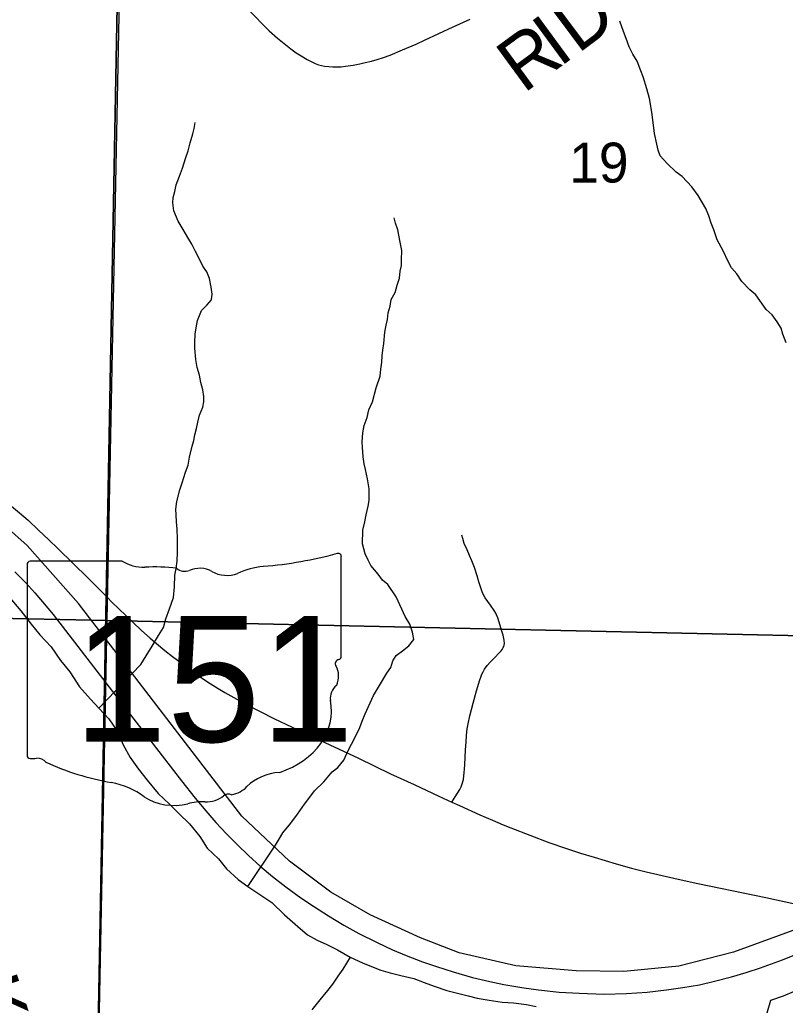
# Model space of a CAD drawing. Extents: x 0 to 34, y 0 to 22.
# Drawn here: x 11.383 to 12.186, y 18.575 to 19.609 of the extents above; entities that cross this region are included whole.
import ezdxf

# ---------------------------------------------------------------- set-up
doc = ezdxf.new("R2010")
doc.units = 0
for name, color, linetype in [('GM_X_Corporation', 7, 'Continuous'), ('GM_X_Major_River', 7, 'Continuous'), ('GM_X_Minor_River', 7, 'Continuous'), ('GM_X_Rail_Line', 7, 'Continuous'), ('GM_X_Section_Text', 7, 'Continuous'), ('GM_X_State_Location', 7, 'Continuous'), ('GM_X_State_Route', 7, 'Continuous'), ('GM_X_State_Shield', 7, 'Continuous'), ('GM_X_Township_Road', 7, 'Continuous'), ('GM_X_Township_Road_Text', 7, 'Continuous')]:
    doc.layers.add(name, color=color, linetype=linetype)

msp = doc.modelspace()

# ---------------------------------------------------------------- linework, layer by layer
at = {"layer": 'GM_X_Corporation'}
for points in [[(11.5001, 20.4), (10.6, 20.4), (10.6, 17.5523), (10.9447, 17.5459), (11.0329, 17.5442), (11.4477, 17.5329), (11.4514, 17.7789), (11.4741, 19.003), (11.486, 19.6423), (11.498, 20.2911)], [(10.6, 20.0026), (10.6, 18.9967), (11.4752, 18.9783), (11.4952, 19.9838)], [(12.5051, 19.9749), (12.4906, 18.9558), (11.4752, 18.9783), (11.4952, 19.9838)], [(10.6, 18.9967), (10.6, 18.0532), (11.4565, 18.0343), (11.4752, 18.9783)], [(11.4752, 18.9783), (12.4906, 18.9558), (12.4638, 18.0185), (11.4565, 18.0343)]]:
    msp.add_lwpolyline(points, close=True, dxfattribs=at)
msp.add_lwpolyline([(16.7661, 20.4), (11.5001, 20.4), (11.498, 20.2911), (11.486, 19.6423), (11.4741, 19.003), (11.4514, 17.7789), (11.4477, 17.5329), (11.8073, 17.526), (12.504, 17.5091), (12.7693, 17.5027), (12.7967, 17.502), (13.2742, 17.4966), (14.0954, 17.4811)], dxfattribs=at)
at = {"layer": 'GM_X_Major_River'}
for points in [[(11.373, 19.0022), (11.3846, 18.9884), (11.3954, 18.9745), (11.4047, 18.9633), (11.4163, 18.9506), (11.4263, 18.9363), (11.436, 18.9244), (11.4461, 18.9086), (11.4577, 18.8959), (11.4665, 18.8862), (11.4769, 18.875), (11.4859, 18.8618), (11.4918, 18.8479), (11.4992, 18.8347), (11.5081, 18.8224), (11.517, 18.8108), (11.5286, 18.7969), (11.5405, 18.7857), (11.5505, 18.7757), (11.5616, 18.7648), (11.5725, 18.7517), (11.5802, 18.7394), (11.5921, 18.7282), (11.6003, 18.7177), (11.6126, 18.7065), (11.6229, 18.6991), (11.6352, 18.6909), (11.6478, 18.6824), (11.6612, 18.6694), (11.6751, 18.6571), (11.6854, 18.6485), (11.6954, 18.643), (11.7057, 18.6382), (11.7167, 18.6327), (11.7301, 18.6249), (11.7431, 18.6191), (11.7526, 18.6151), (11.7621, 18.6114), (11.772, 18.6085), (11.7834, 18.6057), (11.7967, 18.6025), (11.8078, 18.5985), (11.8181, 18.5945), (11.8314, 18.5902), (11.8413, 18.5877), (11.8538, 18.5844)], [(12.1676, 18.5667), (12.1712, 18.58), (12.1847, 18.5844), (12.196, 18.5895)], [(11.8538, 18.5844), (11.8633, 18.5819), (11.8759, 18.5799), (11.8895, 18.5778), (11.9013, 18.5772), (11.9149, 18.5752), (11.9252, 18.5731)]]:
    msp.add_lwpolyline(points, dxfattribs=at)
at = {"layer": 'GM_X_Minor_River'}
for points in [[(12.1873, 19.2697), (12.184, 19.2789), (12.1821, 19.2849), (12.1779, 19.2918), (12.1727, 19.299), (12.1666, 19.3048), (12.1557, 19.32), (12.1493, 19.3254), (12.1409, 19.3341), (12.1357, 19.3421), (12.13, 19.3482), (12.1266, 19.3551), (12.1214, 19.3661), (12.115, 19.3779), (12.1116, 19.3882), (12.1086, 19.3951), (12.1063, 19.4031), (12.1033, 19.4107), (12.095, 19.4244), (12.0883, 19.4335), (12.0784, 19.4442), (12.072, 19.4488), (12.0626, 19.458), (12.0554, 19.466), (12.0531, 19.4717), (12.0516, 19.4781), (12.0494, 19.4892), (12.048, 19.501), (12.0465, 19.5116), (12.0439, 19.5261), (12.0413, 19.5363), (12.0375, 19.5489), (12.0349, 19.555), (12.0312, 19.5653), (12.0266, 19.5725), (12.0229, 19.5801), (12.0195, 19.5889), (12.0169, 19.5965), (12.0131, 19.6071)], [(11.4665, 18.8862), (11.5105, 18.9321), (11.5162, 18.9412), (11.5224, 18.9514), (11.5292, 18.9624), (11.5342, 18.9708), (11.5369, 18.9799), (11.5407, 18.9905), (11.5446, 19.0023), (11.5458, 19.0137), (11.5462, 19.0258), (11.5474, 19.033), (11.5485, 19.0406), (11.549, 19.0501), (11.549, 19.0566), (11.549, 19.0642), (11.5487, 19.0741), (11.548, 19.0817), (11.5476, 19.0893), (11.5473, 19.095), (11.5481, 19.1033), (11.5515, 19.1155), (11.5538, 19.1227), (11.5573, 19.1341), (11.56, 19.1413), (11.5615, 19.1496), (11.5642, 19.1614), (11.5662, 19.1671), (11.5673, 19.1732), (11.5689, 19.1796), (11.5704, 19.1865), (11.572, 19.1937), (11.5754, 19.202), (11.5766, 19.2077), (11.5766, 19.2134), (11.5755, 19.2203), (11.5733, 19.2282), (11.5722, 19.2358), (11.5695, 19.2438), (11.5681, 19.2522), (11.567, 19.264), (11.567, 19.2701), (11.5674, 19.2788), (11.5686, 19.2853), (11.5701, 19.2932), (11.5743, 19.3035), (11.5797, 19.3092), (11.5846, 19.3148), (11.5854, 19.3209), (11.5843, 19.3281), (11.5825, 19.3373), (11.5798, 19.3441), (11.5757, 19.3502), (11.5719, 19.3574), (11.5674, 19.3662), (11.564, 19.3731), (11.5599, 19.3803), (11.555, 19.3887), (11.5497, 19.3974), (11.5452, 19.4081), (11.5441, 19.4165), (11.5445, 19.4222), (11.546, 19.4286), (11.5476, 19.4355), (11.551, 19.4446), (11.5541, 19.4529), (11.5572, 19.4632), (11.5603, 19.4711), (11.5622, 19.4795), (11.5649, 19.489), (11.5664, 19.4947), (11.5676, 19.5007)], [(11.6229, 18.6991), (11.6516, 18.7426), (11.6558, 18.7495), (11.6596, 18.7555), (11.668, 18.7657), (11.6749, 18.7752), (11.6821, 18.7854), (11.6879, 18.793), (11.6928, 18.7995), (11.7023, 18.8089), (11.7111, 18.8195), (11.7172, 18.824), (11.7233, 18.8316), (11.7279, 18.8419), (11.7348, 18.8551), (11.7402, 18.8661), (11.7428, 18.8726), (11.7459, 18.8805), (11.7494, 18.8881), (11.7547, 18.8995), (11.7608, 18.9101), (11.7685, 18.923), (11.7727, 18.9291), (11.775, 18.9359), (11.7784, 18.9416), (11.7849, 18.9465), (11.7917, 18.9518), (11.7967, 18.9582), (11.7956, 18.9662), (11.7926, 18.9746), (11.7877, 18.9826), (11.7843, 18.9902), (11.7783, 19.0031), (11.7696, 19.0161), (11.764, 19.0207), (11.7594, 19.0268), (11.7519, 19.0359), (11.7489, 19.0416), (11.7459, 19.0481), (11.7429, 19.0588), (11.7433, 19.0732), (11.7456, 19.0819), (11.7468, 19.0892), (11.7491, 19.0983), (11.7499, 19.1043), (11.75, 19.1165), (11.7481, 19.1268), (11.7463, 19.1367), (11.7448, 19.1427), (11.7437, 19.15), (11.7429, 19.1602), (11.7426, 19.1659), (11.7434, 19.1751), (11.7449, 19.183), (11.748, 19.1914), (11.7496, 19.1993), (11.7534, 19.2077), (11.7573, 19.2225), (11.7615, 19.2346), (11.7623, 19.2419), (11.7634, 19.2494), (11.7638, 19.2559), (11.7643, 19.262), (11.7654, 19.2688), (11.7666, 19.281), (11.7678, 19.2882), (11.7693, 19.2943), (11.7701, 19.3011), (11.772, 19.3083), (11.7732, 19.3151), (11.7774, 19.3224), (11.7793, 19.3303), (11.7817, 19.3375), (11.7824, 19.3447), (11.784, 19.3508), (11.784, 19.3569), (11.7841, 19.3664), (11.7826, 19.3752), (11.78, 19.3881), (11.7777, 19.3953), (11.7762, 19.401)], [(11.7301, 18.6249), (11.7224, 18.6124), (11.717, 18.6052), (11.7117, 18.5968), (11.7063, 18.59), (11.6983, 18.5802), (11.6899, 18.5699)]]:
    msp.add_lwpolyline(points, dxfattribs=at)
at = {"layer": 'GM_X_Rail_Line'}
for points in [[(12.2022, 18.6557), (12.1321, 18.6303), (12.0749, 18.6156), (12.0173, 18.61), (11.9673, 18.6107), (11.9039, 18.6159), (11.8444, 18.6294), (11.8039, 18.6454), (11.7512, 18.6696), (11.7099, 18.6932), (11.6663, 18.7259), (11.6166, 18.7731), (11.445, 18.9962), (11.3914, 19.0571), (11.3294, 19.1119)], [(11.3785, 19.0292), (11.3898, 19.0178), (11.3993, 19.0073), (11.4075, 18.9978), (11.4185, 18.9845), (11.5032, 18.8747), (11.553, 18.81), (11.5675, 18.792), (11.5786, 18.7785), (11.5892, 18.7663), (11.6005, 18.7544), (11.6116, 18.7431), (11.6235, 18.7316), (11.6358, 18.7204), (11.6487, 18.7098), (11.6626, 18.6988), (11.6784, 18.6873), (11.6926, 18.6778), (11.7073, 18.6683), (11.7233, 18.6587), (11.7393, 18.6499), (11.7584, 18.6404), (11.7745, 18.6327), (11.7889, 18.6267), (11.806, 18.6202), (11.8207, 18.6151), (11.8382, 18.6095), (11.8585, 18.6037), (11.8766, 18.5996), (11.8911, 18.5964), (11.9121, 18.5927), (11.9278, 18.5906), (11.9492, 18.5883), (11.9702, 18.5871), (11.9966, 18.5863), (12.0199, 18.5869), (12.0415, 18.5883), (12.0619, 18.5908), (12.079, 18.5931), (12.0965, 18.5961), (12.1124, 18.5997), (12.13, 18.6043), (12.1456, 18.609), (12.1606, 18.6139), (12.1837, 18.6221), (12.2276, 18.6399)]]:
    msp.add_lwpolyline(points, dxfattribs=at)
at = {"layer": 'GM_X_State_Route'}
for points in [[(11.2749, 19.171), (11.2808, 19.1672), (11.3014, 19.1533), (11.3151, 19.1438), (11.3325, 19.1312), (11.3484, 19.1196), (11.3612, 19.1096), (11.3708, 19.1019), (11.3832, 19.0913), (11.3922, 19.0834), (11.4032, 19.0731), (11.414, 19.0628), (11.4236, 19.0537), (11.4552, 19.0226), (11.4647, 19.0133), (11.4755, 19.0023), (11.4801, 18.9977)], [(11.4801, 18.9977), (11.502, 18.9765), (11.5112, 18.9678), (11.5203, 18.9597), (11.5358, 18.9468), (11.5437, 18.9406), (11.5555, 18.9316), (11.5694, 18.9215), (11.5751, 18.9175), (11.5832, 18.9122), (11.5916, 18.9069), (11.5987, 18.9027), (11.6111, 18.8957), (11.6212, 18.8903), (11.6358, 18.8827), (11.6501, 18.8756), (11.6883, 18.8574), (11.7388, 18.8337), (11.7725, 18.8175), (11.7973, 18.8062), (11.8232, 18.7938), (11.8367, 18.7876), (11.8448, 18.784), (11.8662, 18.7743), (11.8794, 18.7686), (11.8905, 18.7639), (11.8987, 18.7606), (11.9385, 18.7454), (11.957, 18.7391), (11.9717, 18.7343), (11.9861, 18.7298), (12.0091, 18.723), (12.0253, 18.7185), (12.0407, 18.7145), (12.0575, 18.7107), (12.0742, 18.7068), (12.0949, 18.7023), (12.166, 18.6876), (12.1964, 18.6811)]]:
    msp.add_lwpolyline(points, dxfattribs=at)
at = {"layer": 'GM_X_State_Shield'}
for p, q in [((11.491, 19.0404), (11.3945, 19.0404)), ((11.7208, 18.9407), (11.7208, 19.0454)), ((11.3913, 19.037), (11.3913, 18.8369)), ((11.7208, 18.9407), (11.7208, 18.9407))]:
    msp.add_line(p, q, dxfattribs=at)
for centre, major_axis, start_param, end_param in [((11.395, 19.0374), (0.00382, 0), 1.712693, 3.28349), ((11.514, 19.0637), (0.037, 0), 4.042523, 4.731795), ((11.6034, 19.3133), (0.3495, 0), 4.814394, 5.042369), ((11.7172, 19.0458), (0.00367, 0), 6.141152, 7.989035), ((11.5263, 18.9281), (0.133, 0), 1.404758, 1.657858), ((11.5565, 19.0385), (0.0107, 0), 3.836095, 5.185415), ((11.5722, 19.0153), (0.0222, 0), 0.950623, 2.079405), ((11.6008, 19.047), (0.0267, 0), 4.081561, 5.145723), ((11.648, 18.9793), (0.0703, 0), 1.699011, 2.107814), ((11.72, 18.933), (0.00568, 0), 1.883978, 3.671073), ((11.7169, 18.9403), (0.00393, 0), 5.05454, 6.418171), ((11.6839, 18.9198), (0.0341, 0), 5.934695, 6.695948), ((11.734, 18.8969), (0.0248, 0), 2.387724, 3.262537), ((11.623, 18.8836), (0.0874, 0), 5.101752, 6.440018), ((11.3951, 18.8364), (0.00385, 0), 3.00124, 4.508301), ((11.3957, 18.8569), (0.0294, 0), 4.665946, 4.897461), ((11.4017, 18.8253), (0.0106, 0), 0.519207, 1.627899), ((11.5355, 19.0051), (0.2524, 0), 4.195997, 4.488961), ((11.6599, 18.7807), (0.0479, 0), 1.647645, 2.488434), ((11.4602, 18.747), (0.079, 0), 0.823519, 1.323587), ((11.5992, 18.8175), (0.0282, 0), 4.937069, 5.64225), ((11.5457, 18.8243), (0.0501, 0), 4.026481, 4.996735), ((11.5783, 18.8093), (0.0267, 0), 4.691044, 5.507374), ((11.6024, 18.79), (0.00752, 0), 1.147584, 2.315152), ((11.5746, 18.7551), (0.0412, 0), 1.495662, 1.94098)]:
    msp.add_ellipse(centre, major_axis=major_axis, ratio=0.8, start_param=start_param, end_param=end_param, dxfattribs=at)
at = {"layer": 'GM_X_Township_Road'}
for points in [[(11.6231, 19.6195), (11.6451, 19.597), (11.654, 19.5893), (11.6625, 19.5822), (11.6679, 19.578), (11.6736, 19.5741), (11.6786, 19.5709), (11.6851, 19.5671), (11.6892, 19.5648), (11.6932, 19.5629), (11.6967, 19.5615), (11.6999, 19.5607), (11.7031, 19.5601), (11.7076, 19.5595), (11.712, 19.5592), (11.7206, 19.5594), (11.7251, 19.5599), (11.7332, 19.5612), (11.7401, 19.5626), (11.7459, 19.5638), (11.7524, 19.5654), (11.7583, 19.567), (11.7652, 19.5691), (11.7721, 19.5717), (11.785, 19.577), (11.7992, 19.5831), (11.8081, 19.5871), (11.838, 19.6011), (11.8558, 19.6094)], [(11.8367, 18.7876), (11.8402, 18.7933), (11.8451, 18.8011), (11.8464, 18.8038), (11.8475, 18.8069), (11.8488, 18.8115), (11.8494, 18.8152), (11.8496, 18.8186), (11.8502, 18.827), (11.8512, 18.8427), (11.8516, 18.8505), (11.8522, 18.8581), (11.8529, 18.8645), (11.8538, 18.8697), (11.8557, 18.8783), (11.859, 18.8914), (11.8625, 18.9046), (11.866, 18.9162), (11.867, 18.9189), (11.8682, 18.9218), (11.8695, 18.9243), (11.8711, 18.9272), (11.8739, 18.9311), (11.8774, 18.935), (11.8796, 18.9375), (11.8883, 18.9466), (11.8894, 18.948), (11.8905, 18.9498), (11.8912, 18.9511), (11.8917, 18.9524), (11.8919, 18.954), (11.8916, 18.9577), (11.8904, 18.963), (11.8894, 18.9661), (11.8848, 18.9812), (11.8836, 18.9841), (11.8827, 18.986), (11.8811, 18.9888), (11.8773, 18.9944), (11.8718, 19.0021), (11.87, 19.0052), (11.8686, 19.0085), (11.8665, 19.0146), (11.8652, 19.0187), (11.8633, 19.0251), (11.8605, 19.0338), (11.8577, 19.041), (11.8553, 19.0466), (11.8527, 19.0523), (11.8497, 19.0592), (11.8481, 19.0642), (11.8471, 19.068)]]:
    msp.add_lwpolyline(points, dxfattribs=at)

# ---------------------------------------------------------------- texts
at = {"layer": 'GM_X_Section_Text'}
msp.add_text('19', height=0.04186, rotation=0, dxfattribs=at).set_placement((11.9598, 19.4379))
at = {"layer": 'GM_X_State_Location'}
for s, p in [('s', (11.5524, 18.9236)), ('r', (11.5523, 18.9236))]:
    msp.add_text(s, height=0.000189, dxfattribs=at).set_placement(p)
msp.add_text('151', height=0.000189, rotation=0, dxfattribs=at).set_placement((11.4855, 18.9098))
at = {"layer": 'GM_X_State_Shield'}
msp.add_text('151', height=0.13184, dxfattribs=at).set_placement((11.4398, 18.851))
at = {"layer": 'GM_X_Township_Road_Text'}
for s, rotation, p in [('D', 36.7752, (11.9688, 19.5724)), ('I', 36.2579, (11.9496, 19.5583)), ('R', 36.2087, (11.9119, 19.5307)), ('K', 287.5629, (11.3246, 18.5957))]:
    msp.add_text(s, height=0.0568, rotation=rotation, dxfattribs=at).set_placement(p)

doc.saveas('drawing.dxf')
